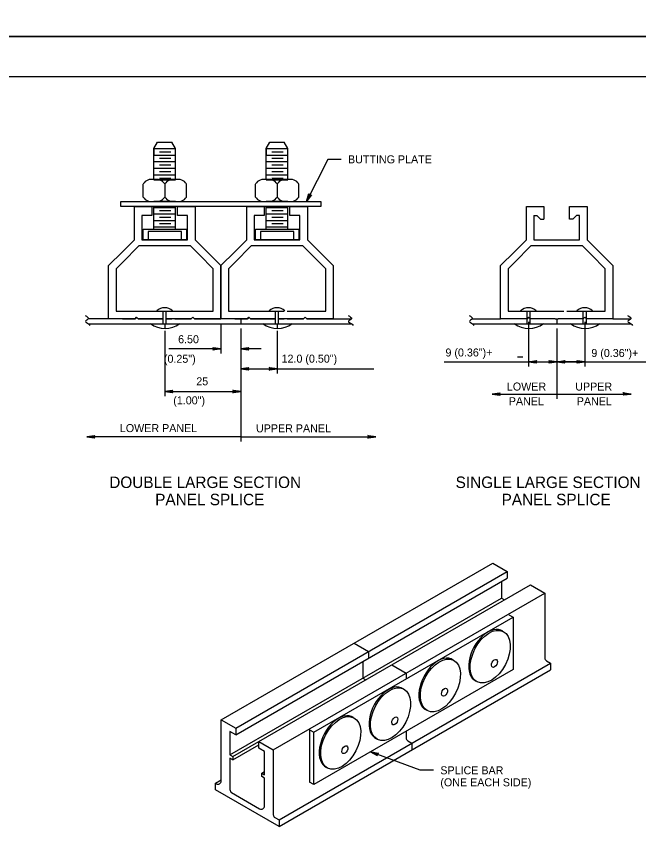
# Model space of a CAD drawing. Extents: x 650495 to 651400, y 297864 to 299646.
# Drawn here: x 650728.4 to 650961.5, y 298749.7 to 299059.1 of the extents above; entities that cross this region are included whole.
import ezdxf

# ---------------------------------------------------------------- set-up
doc = ezdxf.new("R2010")
doc.units = 0
for name, color, linetype in [('1', 7, 'Continuous'), ('2', 7, 'Continuous'), ('3', 7, 'Continuous'), ('PLT-BNDY', 7, 'Continuous')]:
    doc.layers.add(name, color=color, linetype=linetype)

# ---------------------------------------------------------------- blocks, each defined once
blk = doc.blocks.new('RARROW')
at = {"layer": '3'}
blk.add_lwpolyline([(-2.2695, 0.285), (-2.184875, 0.12075), (0, 0), (-2.2695, 0.285), (-2.38575, 0.384625), (0, 0), (-2.183125, -0.108), (-2.262875, -0.2705), (0, 0), (-2.38575, -0.379125), (-2.262875, -0.2705)], dxfattribs=at)

msp = doc.modelspace()

# ---------------------------------------------------------------- linework, layer by layer
at = {"layer": '1'}
msp.add_line((650535.31, 299036.63), (651321.31, 299036.63), dxfattribs=at)
at = {"layer": '2'}
for p, q in [((650779.9, 299009.62), (650781.28, 299012)), ((650779.9, 299009.62), (650788.03, 299009.62)), ((650779.9, 299009.62), (650779.9, 299007.12)), ((650779.9, 298998), (650779.9, 299009.62)), ((650781.28, 299012), (650786.65, 299012)), ((650788.03, 299009.62), (650786.65, 299012)), ((650788.03, 298998), (650788.03, 299009.62)), ((650822.03, 299009.62), (650823.4, 299012)), ((650822.03, 299009.62), (650830.15, 299009.62)), ((650822.03, 299009.62), (650822.03, 299007.12)), ((650822.03, 298998), (650822.03, 299009.62)), ((650823.4, 299012), (650828.78, 299012)), ((650830.15, 299009.62), (650828.78, 299012)), ((650830.15, 298998), (650830.15, 299009.62)), ((650779.9, 299007.12), (650788.03, 299007.12)), ((650782.03, 299008.37), (650786.28, 299008.37)), ((650782.03, 299006), (650786.28, 299006)), ((650822.03, 299007.12), (650830.15, 299007.12)), ((650824.15, 299008.37), (650828.4, 299008.37)), ((650824.15, 299006), (650828.4, 299006)), ((650779.9, 299004.75), (650788.03, 299004.75)), ((650782.03, 299003.5), (650786.28, 299003.5)), ((650822.03, 299004.75), (650830.15, 299004.75)), ((650824.15, 299003.5), (650828.4, 299003.5)), ((650779.9, 299002.25), (650788.03, 299002.25)), ((650779.9, 298999.87), (650788.03, 298999.87)), ((650782.03, 299001.12), (650786.28, 299001.12)), ((650822.03, 299002.25), (650830.15, 299002.25)), ((650822.03, 298999.87), (650830.15, 298999.87)), ((650824.15, 299001.12), (650828.4, 299001.12)), ((650779.9, 298998), (650788.03, 298998)), ((650788.03, 298998), (650779.9, 298998)), ((650782.03, 298998.62), (650786.28, 298998.62)), ((650822.03, 298998), (650830.15, 298998)), ((650830.15, 298998), (650822.03, 298998)), ((650824.15, 298998.62), (650828.4, 298998.62)), ((650775.9, 298991.5), (650775.9, 298996.37)), ((650784.03, 298996.37), (650784.03, 298991.5)), ((650792.15, 298991.5), (650792.15, 298996.37)), ((650818.03, 298991.5), (650818.03, 298996.37)), ((650826.15, 298996.37), (650826.15, 298991.5)), ((650834.28, 298991.5), (650834.28, 298996.37)), ((650788.03, 298989.87), (650779.9, 298989.87)), ((650779.9, 298979.5), (650779.9, 298988)), ((650779.9, 298987.62), (650788.03, 298987.62)), ((650788.03, 298979.5), (650788.03, 298988)), ((650830.15, 298989.87), (650822.03, 298989.87)), ((650822.03, 298979.5), (650822.03, 298988)), ((650822.03, 298987.62), (650830.15, 298987.62)), ((650830.15, 298979.5), (650830.15, 298988)), ((650919.53, 298977.12), (650919.53, 298988)), ((650919.53, 298988), (650926.03, 298988)), ((650926.03, 298988), (650926.03, 298983.25)), ((650935.66, 298983.25), (650935.66, 298988)), ((650935.66, 298988), (650942.28, 298988)), ((650942.28, 298988), (650942.28, 298978.25)), ((650779.9, 298985.25), (650788.03, 298985.25)), ((650782.03, 298986.5), (650786.28, 298986.5)), ((650822.03, 298985.25), (650830.15, 298985.25)), ((650824.15, 298986.5), (650828.4, 298986.5)), ((650922.28, 298984.62), (650923.41, 298984.62)), ((650922.28, 298984.62), (650922.28, 298975.5)), ((650924.78, 298983.25), (650923.41, 298984.62)), ((650936.91, 298983.25), (650938.28, 298984.62)), ((650939.41, 298984.62), (650938.28, 298984.62)), ((650939.41, 298975.5), (650939.41, 298984.62)), ((650779.9, 298982.75), (650788.03, 298982.75)), ((650782.03, 298984), (650786.28, 298984)), ((650782.03, 298981.62), (650786.28, 298981.62)), ((650822.03, 298982.75), (650830.15, 298982.75)), ((650824.15, 298984), (650828.4, 298984)), ((650824.15, 298981.62), (650828.4, 298981.62)), ((650924.78, 298983.25), (650926.03, 298983.25)), ((650936.91, 298983.25), (650935.66, 298983.25)), ((650775.9, 298975.5), (650775.9, 298979.5)), ((650775.9, 298979.5), (650792.15, 298979.5)), ((650779.9, 298980.37), (650788.03, 298980.37)), ((650792.15, 298979.5), (650792.15, 298975.5)), ((650818.03, 298975.5), (650818.03, 298979.5)), ((650818.03, 298979.5), (650834.28, 298979.5)), ((650822.03, 298980.37), (650830.15, 298980.37)), ((650834.28, 298979.5), (650834.28, 298975.5)), ((650792.15, 298975.5), (650775.9, 298975.5)), ((650834.28, 298975.5), (650818.03, 298975.5)), ((650922.28, 298975.5), (650939.41, 298975.5)), ((650783.4, 298944), (650783.4, 298948.75)), ((650784.53, 298944), (650784.53, 298948.75)), ((650825.53, 298944), (650825.53, 298948.75)), ((650826.65, 298944), (650826.65, 298948.75)), ((650919.78, 298944), (650919.78, 298948.75)), ((650920.91, 298944), (650920.91, 298948.75)), ((650940.78, 298944), (650940.78, 298948.75)), ((650942.03, 298944), (650942.03, 298948.75)), ((650762.9, 298945.87), (650755.28, 298945.87)), ((650805.03, 298944.12), (650805.03, 298932.93)), ((650812.53, 298945.87), (650812.53, 298944)), ((650847.15, 298945.87), (650853.9, 298945.87)), ((650899.16, 298945.87), (650909.78, 298945.87)), ((650920.28, 298944.75), (650920.28, 298927.95)), ((650930.28, 298945.87), (650931.41, 298945.87)), ((650930.91, 298945.87), (650930.91, 298944)), ((650941.41, 298944.75), (650941.41, 298927.95)), ((650951.91, 298945.87), (650958.66, 298945.87)), ((650755.28, 298944), (650854.03, 298944)), ((650784.03, 298944), (650784.03, 298942.26)), ((650784.03, 298941.41), (650784.03, 298916.88)), ((650812.53, 298942.25), (650812.53, 298916.88)), ((650825.53, 298944), (650826.65, 298944)), ((650826.15, 298944), (650826.15, 298942.26)), ((650826.15, 298941.36), (650826.15, 298925.41)), ((650899.28, 298944), (650958.78, 298944)), ((650919.78, 298944), (650920.91, 298944)), ((650930.28, 298944), (650931.41, 298944)), ((650930.91, 298942.25), (650930.91, 298927.95)), ((650930.91, 298942.25), (650930.91, 298915.95)), ((650940.78, 298944), (650942.03, 298944)), ((650805.03, 298934.68), (650785.55, 298934.68)), ((650820.12, 298934.68), (650812.53, 298934.68)), ((650888.65, 298929.7), (650973, 298929.7)), ((650916.17, 298931.58), (650918.16, 298931.58)), ((650941.41, 298929.7), (650930.91, 298929.7)), ((650941.41, 298929.7), (650941.41, 298929.7)), ((650812.53, 298927.16), (650862.34, 298927.16)), ((650784.03, 298918.63), (650812.53, 298918.63)), ((650812.53, 298916.88), (650812.53, 298899.93)), ((650906.66, 298917.7), (650930.91, 298917.7)), ((650930.91, 298917.7), (650958.78, 298917.7)), ((650812.53, 298901.68), (650754.78, 298901.68)), ((650812.53, 298901.68), (650863.13, 298901.68)), ((650805.16, 298795.62), (650906.92, 298854.37)), ((650810.57, 298792.49), (650912.33, 298851.24)), ((650810.57, 298789.99), (650912.33, 298848.74)), ((650819.24, 298787.49), (650920.99, 298846.24)), ((650824.65, 298784.37), (650926.41, 298843.12)), ((650808.41, 298782.49), (650910.17, 298841.24)), ((650912.87, 298835.02), (650914.5, 298834.08)), ((650910.72, 298828.82), (650910.72, 298828.82)), ((650892.05, 298818.04), (650892.05, 298818.04)), ((650826.81, 298758.12), (650928.57, 298816.87)), ((650826.81, 298755.62), (650928.57, 298814.37)), ((650914.5, 298814.52), (650914.5, 298814.52)), ((650900.62, 298810.1), (650900.62, 298810.1)), ((650873.38, 298807.26), (650873.38, 298807.26)), ((650895.82, 298803.74), (650895.82, 298803.74)), ((650881.95, 298799.32), (650881.95, 298799.32)), ((650805.16, 298795.62), (650805.16, 298795.62)), ((650854.7, 298796.48), (650854.7, 298796.48)), ((650877.15, 298792.96), (650877.15, 298792.96)), ((650838.18, 298791.89), (650838.18, 298772.33)), ((650838.18, 298791.89), (650839.8, 298790.95)), ((650809.49, 298781.87), (650819.24, 298787.49)), ((650809.49, 298780.62), (650819.24, 298786.24)), ((650863.28, 298788.54), (650863.28, 298788.54)), ((650858.48, 298782.17), (650858.48, 298782.17)), ((650844.6, 298777.76), (650844.6, 298777.76)), ((650820.32, 298775.62), (650821.4, 298776.24)), ((650803, 298771.87), (650805.16, 298773.12)), ((650839.8, 298771.39), (650838.18, 298772.33)), ((650839.8, 298771.39), (650839.8, 298771.39)), ((650809.03, 298768.38), (650819.53, 298762.33))]:
    msp.add_line(p, q, dxfattribs=at)
for points in [[(650850.15, 299005.5), (650845.15, 299005.5), (650837.09, 298989.87)], [(650772.65, 298977.12), (650772.65, 298988), (650779.15, 298988), (650779.15, 298984.62), (650775.4, 298984.62), (650775.4, 298977.12)], [(650792.53, 298978.25), (650792.53, 298984.62), (650788.78, 298984.62), (650788.78, 298988), (650795.4, 298988), (650795.4, 298978.25)], [(650814.78, 298977.12), (650814.78, 298988), (650821.28, 298988), (650821.28, 298984.62), (650817.53, 298984.62), (650817.53, 298977.12)], [(650834.65, 298978.25), (650834.65, 298984.62), (650830.9, 298984.62), (650830.9, 298988), (650837.53, 298988), (650837.53, 298978.25)], [(650787.78, 298975.5), (650792.53, 298975.5), (650792.53, 298978.25)], [(650795.4, 298978.25), (650795.4, 298975.5), (650801.03, 298969.87)], [(650829.9, 298975.5), (650834.65, 298975.5), (650834.65, 298978.25)], [(650837.53, 298978.25), (650837.53, 298975.5), (650843.15, 298969.87)], [(650942.28, 298978.25), (650942.28, 298975.5), (650947.91, 298969.87)], [(650768.15, 298971), (650772.65, 298975.5), (650772.65, 298977.12)], [(650775.4, 298977.12), (650775.4, 298975.5), (650782.78, 298975.5)], [(650782.78, 298975.5), (650784.03, 298975.5)], [(650784.03, 298975.5), (650787.78, 298975.5)], [(650810.28, 298971), (650814.78, 298975.5), (650814.78, 298977.12)], [(650817.53, 298977.12), (650817.53, 298975.5), (650824.9, 298975.5)], [(650824.9, 298975.5), (650826.15, 298975.5)], [(650826.15, 298975.5), (650829.9, 298975.5)], [(650915.03, 298971), (650919.53, 298975.5), (650919.53, 298977.12)], [(650930.91, 298975.5), (650934.66, 298975.5)], [(650774.28, 298973.25), (650768.15, 298967)], [(650782.78, 298973.25), (650774.28, 298973.25)], [(650784.03, 298973.25), (650782.78, 298973.25)], [(650787.78, 298973.25), (650784.03, 298973.25)], [(650793.65, 298973.25), (650787.78, 298973.25)], [(650797.03, 298969.87), (650793.65, 298973.25)], [(650816.4, 298973.25), (650810.28, 298967)], [(650824.9, 298973.25), (650816.4, 298973.25)], [(650826.15, 298973.25), (650824.9, 298973.25)], [(650829.9, 298973.25), (650826.15, 298973.25)], [(650835.78, 298973.25), (650829.9, 298973.25)], [(650839.15, 298969.87), (650835.78, 298973.25)], [(650921.16, 298973.25), (650915.03, 298967)], [(650929.66, 298973.25), (650921.16, 298973.25)], [(650930.91, 298973.25), (650929.66, 298973.25)], [(650934.66, 298973.25), (650930.91, 298973.25)], [(650940.53, 298973.25), (650934.66, 298973.25)], [(650943.91, 298969.87), (650940.53, 298973.25)], [(650768.15, 298945.87), (650762.9, 298945.87), (650762.9, 298965.87), (650768.15, 298971)], [(650802.15, 298955.62), (650802.15, 298964.62), (650797.03, 298969.87)], [(650801.03, 298969.87), (650805.03, 298965.87), (650805.03, 298955.62)], [(650810.28, 298945.87), (650805.03, 298945.87), (650805.03, 298965.87), (650810.28, 298971)], [(650844.28, 298955.62), (650844.28, 298964.62), (650839.15, 298969.87)], [(650843.15, 298969.87), (650847.15, 298965.87), (650847.15, 298955.62)], [(650915.03, 298945.87), (650909.78, 298945.87), (650909.78, 298965.87), (650915.03, 298971)], [(650949.03, 298955.62), (650949.03, 298964.62), (650943.91, 298969.87)], [(650947.91, 298969.87), (650951.91, 298965.87), (650951.91, 298955.62)], [(650768.15, 298967), (650765.78, 298964.62), (650765.78, 298948.75), (650768.15, 298948.75)], [(650810.28, 298967), (650807.9, 298964.62), (650807.9, 298948.75), (650810.28, 298948.75)], [(650915.03, 298967), (650912.66, 298964.62), (650912.66, 298948.75), (650915.03, 298948.75)], [(650787.78, 298948.75), (650802.15, 298948.75), (650802.15, 298955.62)], [(650805.03, 298955.62), (650805.03, 298945.87), (650795.15, 298945.87), (650794.53, 298946.5), (650793.9, 298945.87), (650787.78, 298945.87)], [(650829.9, 298948.75), (650844.28, 298948.75), (650844.28, 298955.62)], [(650847.15, 298955.62), (650847.15, 298945.87), (650837.28, 298945.87), (650836.65, 298946.5), (650836.03, 298945.87), (650829.9, 298945.87)], [(650934.66, 298948.75), (650949.03, 298948.75), (650949.03, 298955.62)], [(650951.91, 298955.62), (650951.91, 298945.87), (650942.03, 298945.87), (650941.41, 298946.5), (650940.78, 298945.87), (650934.66, 298945.87)], [(650768.15, 298948.75), (650784.03, 298948.75)], [(650784.03, 298948.75), (650786.65, 298948.75)], [(650786.65, 298948.75), (650787.78, 298948.75)], [(650810.28, 298948.75), (650826.15, 298948.75)], [(650826.15, 298948.75), (650828.78, 298948.75)], [(650915.03, 298948.75), (650930.91, 298948.75)], [(650930.91, 298948.75), (650933.53, 298948.75)], [(650768.15, 298945.87), (650762.9, 298945.87)], [(650768.15, 298945.87), (650772.9, 298945.87), (650773.4, 298946.5), (650774.03, 298945.87), (650783.4, 298945.87)], [(650783.4, 298945.87), (650774.03, 298945.87), (650773.4, 298946.5), (650772.9, 298945.87), (650768.15, 298945.87)], [(650784.53, 298945.87), (650786.65, 298945.87)], [(650786.65, 298945.87), (650784.53, 298945.87)], [(650787.78, 298945.87), (650786.65, 298945.87)], [(650787.78, 298945.87), (650786.65, 298945.87)], [(650787.78, 298945.87), (650793.9, 298945.87), (650794.53, 298946.5), (650795.15, 298945.87), (650805.03, 298945.87)], [(650810.28, 298945.87), (650805.03, 298945.87)], [(650810.28, 298945.87), (650815.03, 298945.87), (650815.53, 298946.5), (650816.15, 298945.87), (650825.53, 298945.87)], [(650825.53, 298945.87), (650816.15, 298945.87), (650815.53, 298946.5), (650815.03, 298945.87), (650810.28, 298945.87)], [(650826.65, 298945.87), (650828.78, 298945.87)], [(650826.65, 298945.87), (650828.78, 298945.87)], [(650828.78, 298945.87), (650826.65, 298945.87)], [(650829.9, 298945.87), (650828.78, 298945.87)], [(650829.9, 298945.87), (650828.78, 298945.87)], [(650829.9, 298945.87), (650828.78, 298945.87)], [(650829.9, 298945.87), (650836.03, 298945.87), (650836.65, 298946.5), (650837.28, 298945.87), (650847.15, 298945.87)], [(650915.03, 298945.87), (650909.78, 298945.87)], [(650930.28, 298945.87), (650920.91, 298945.87), (650920.28, 298946.5), (650919.78, 298945.87), (650915.03, 298945.87)], [(650933.53, 298945.87), (650931.41, 298945.87)], [(650934.66, 298945.87), (650933.53, 298945.87)], [(650906.92, 298854.37), (650912.33, 298851.24), (650912.33, 298848.74)], [(650910.17, 298847.49), (650910.17, 298841.24), (650911.25, 298840.62)], [(650920.99, 298846.24), (650926.41, 298843.12), (650926.41, 298818.84)], [(650839.8, 298790.95), (650914.5, 298834.08), (650914.5, 298814.52), (650839.8, 298771.39), (650839.8, 298790.95)], [(650854.96, 298824.37), (650860.37, 298821.24), (650860.37, 298818.74)], [(650858.21, 298817.49), (650858.21, 298811.24), (650859.29, 298810.62)], [(650927.03, 298817.76), (650928.57, 298816.87), (650928.57, 298814.37)], [(650869.03, 298816.24), (650874.44, 298813.12), (650874.44, 298810.95)], [(650805.16, 298772.78), (650805.16, 298795.62), (650810.57, 298792.49), (650810.57, 298789.99), (650808.41, 298791.24), (650808.41, 298782.49), (650809.49, 298781.87), (650809.49, 298780.62), (650808.41, 298781.24), (650808.41, 298769.47)], [(650874.44, 298791.39), (650874.44, 298788.84)], [(650821.4, 298763.41), (650821.4, 298773.74), (650820.32, 298774.37), (650820.32, 298775.62), (650821.4, 298774.99), (650821.4, 298783.74), (650819.24, 298784.99), (650819.24, 298787.49), (650824.65, 298784.37), (650824.65, 298760.09)], [(650875.07, 298787.76), (650876.61, 298786.87), (650876.61, 298784.37)], [(650884.71, 298776.81), (650879.71, 298776.81), (650861.03, 298783.65)], [(650825.27, 298759.01), (650826.81, 298758.12), (650826.81, 298755.62), (650803, 298769.37), (650803, 298771.87), (650803.29, 298771.7)]]:
    msp.add_lwpolyline(points, dxfattribs=at)
for points in [[(650767.53, 298988), (650767.53, 298989.87), (650842.53, 298989.87), (650842.53, 298988)], [(650790.28, 298975.5), (650790.28, 298978.62), (650777.78, 298978.62), (650777.78, 298975.5)], [(650832.4, 298975.5), (650832.4, 298978.62), (650819.9, 298978.62), (650819.9, 298975.5)]]:
    msp.add_lwpolyline(points, close=True, dxfattribs=at)
for centre, radius, start, end in [((650779.04, 298994.31), 3.8, 76.6866, 146.9162), ((650780.79, 298994.31), 3.8, 33.0838, 103.3134), ((650787.17, 298994.31), 3.8, 76.6866, 146.9162), ((650788.92, 298994.31), 3.8, 33.0838, 103.3134), ((650821.16, 298994.31), 3.8, 76.6866, 146.9162), ((650822.92, 298994.31), 3.8, 33.0838, 103.3134), ((650829.29, 298994.31), 3.8, 76.6866, 146.9162), ((650831.04, 298994.31), 3.8, 33.0838, 103.3134), ((650779.04, 298993.58), 3.8, 213.0838, 283.3134), ((650780.79, 298993.58), 3.8, 256.6866, 326.9162), ((650787.17, 298993.58), 3.8, 213.0838, 283.3134), ((650788.92, 298993.58), 3.8, 256.6866, 326.9162), ((650821.16, 298993.58), 3.8, 213.0838, 283.3134), ((650822.92, 298993.58), 3.8, 256.6866, 326.9162), ((650829.29, 298993.58), 3.8, 213.0838, 283.3134), ((650831.04, 298993.58), 3.8, 256.6866, 326.9162), ((650783.95, 298945.77), 4.23, 45.7805, 134.2195), ((650826.07, 298945.77), 4.23, 45.7805, 134.2195), ((650920.28, 298945.77), 4.23, 45.7805, 134.2195), ((650941.37, 298945.77), 4.23, 45.7805, 134.2195), ((650784.11, 298951.27), 9.01, 232.6949, 307.3051), ((650826.23, 298951.27), 9.01, 232.6949, 307.3051), ((650920.44, 298951.27), 9.01, 232.6949, 307.3051), ((650941.53, 298951.27), 9.01, 232.6949, 307.3051), ((650927.66, 298818.84), 1.25, 180, 239.9993), ((650875.69, 298788.84), 1.25, 180, 239.9993), ((650803.91, 298772.78), 1.25, 239.9993, 0), ((650809.66, 298769.47), 1.25, 180, 240.0002), ((650820.15, 298763.41), 1.25, 239.9999, 0), ((650825.9, 298760.09), 1.25, 180, 239.9993)]:
    msp.add_arc(centre, radius, start, end, dxfattribs=at)
for centre in [(650905.4, 298819.62), (650886.73, 298808.83), (650868.06, 298798.05), (650849.38, 298787.27)]:
    msp.add_ellipse(centre, major_axis=(4.9, 9.45), ratio=0.602781, start_param=6.207238, end_param=9.446163, dxfattribs=at)
for centre, major_axis in [((650905.94, 298819.3), (4.9, 9.45)), ((650887.27, 298808.52), (4.9, 9.45)), ((650907.52, 298816.78), (0.74, 1.42)), ((650868.6, 298797.74), (4.9, 9.45)), ((650888.85, 298806), (0.74, 1.42)), ((650849.92, 298786.96), (4.9, 9.45)), ((650870.17, 298795.22), (0.74, 1.42)), ((650851.5, 298784.44), (0.74, 1.42))]:
    msp.add_ellipse(centre, major_axis=major_axis, ratio=0.602781, dxfattribs=at)
for points in [[(650754.15, 298947.12), (650755.28, 298945.87), (650754.28, 298944.87), (650755.4, 298944), (650755.9, 298943.37)], [(650852.65, 298947.12), (650853.9, 298945.87), (650852.78, 298944.87), (650854.03, 298944), (650854.53, 298943.37)], [(650898.03, 298947.12), (650899.16, 298945.87), (650898.16, 298944.87), (650899.28, 298944), (650899.78, 298943.37)], [(650957.41, 298947.12), (650958.66, 298945.87), (650957.53, 298944.87), (650958.78, 298944), (650959.28, 298943.37)]]:
    msp.add_spline(points, degree=3, dxfattribs=at)
at = {"layer": 'PLT-BNDY'}
for points in [[(650495.31, 299645.63), (651336.31, 299645.63), (651336.31, 299051.63), (650495.31, 299051.63)], [(650495.31, 299051.63), (651336.31, 299051.63), (651336.31, 298457.63), (650495.31, 298457.63)]]:
    msp.add_lwpolyline(points, close=True, dxfattribs=at)

# ---------------------------------------------------------------- block references
at = {"layer": '2', "xscale": 1.2574347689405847, "yscale": 1.3092961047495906}
for p, rotation in [((650837.09, 298989.87), -117.30666422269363), ((650812.53, 298934.68), 180), ((650920.28, 298929.7), 180), ((650930.91, 298929.7), 180), ((650812.53, 298927.16), 180), ((650784.03, 298918.63), 180), ((650906.66, 298917.7), 180), ((650754.78, 298901.68), 180), ((650861.03, 298783.65), 159.89547322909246)]:
    msp.add_blockref('RARROW', p, dxfattribs=dict(at, rotation=rotation))
for p in [(650805.03, 298934.68), (650930.91, 298929.7), (650941.41, 298929.7), (650826.15, 298927.16), (650812.53, 298918.63), (650958.78, 298917.7), (650863.13, 298901.68)]:
    msp.add_blockref('RARROW', p, dxfattribs=at)

# ---------------------------------------------------------------- texts
at = {"layer": '2'}
for s, height, p in [('BUTTING PLATE', 2.9992, (650852.65, 299004.12)), ('6.50 ', 3, (650788.98, 298936.72)), ('9 (0.36")+', 3, (650889.18, 298931.76)), ('9 (0.36")+', 3, (650943.85, 298931.57)), (' (0.25")', 3, (650782.54, 298929.4)), ('12.0 (0.50")', 3, (650827.75, 298929.45)), ('25', 3, (650795.78, 298920.96)), ('LOWER', 2.999, (650912.2, 298919)), ('UPPER', 2.999, (650937.82, 298918.98)), (' (1.00")', 3, (650786.05, 298913.82)), ('PANEL', 2.999, (650912.91, 298913.51)), ('PANEL', 2.999, (650938.38, 298913.49)), ('LOWER PANEL', 2.9992, (650767.15, 298903.43)), ('UPPER PANEL', 2.9992, (650818.17, 298903.34)), ('DOUBLE LARGE SECTION', 4.3, (650763.17, 298882.48)), ('SINGLE LARGE SECTION', 4.3, (650892.99, 298882.48)), ('PANEL SPLICE', 4.3, (650780.39, 298876.03)), ('PANEL SPLICE', 4.3, (650910.21, 298876.03))]:
    msp.add_text(s, height=height, dxfattribs=at).set_placement(p)
at = {"layer": '3'}
for s, p in [('SPLICE BAR', (650887.26, 298775.22)), ('(ONE EACH SIDE)', (650887.26, 298770.72))]:
    msp.add_text(s, height=3, dxfattribs=at).set_placement(p)

doc.saveas('drawing.dxf')
